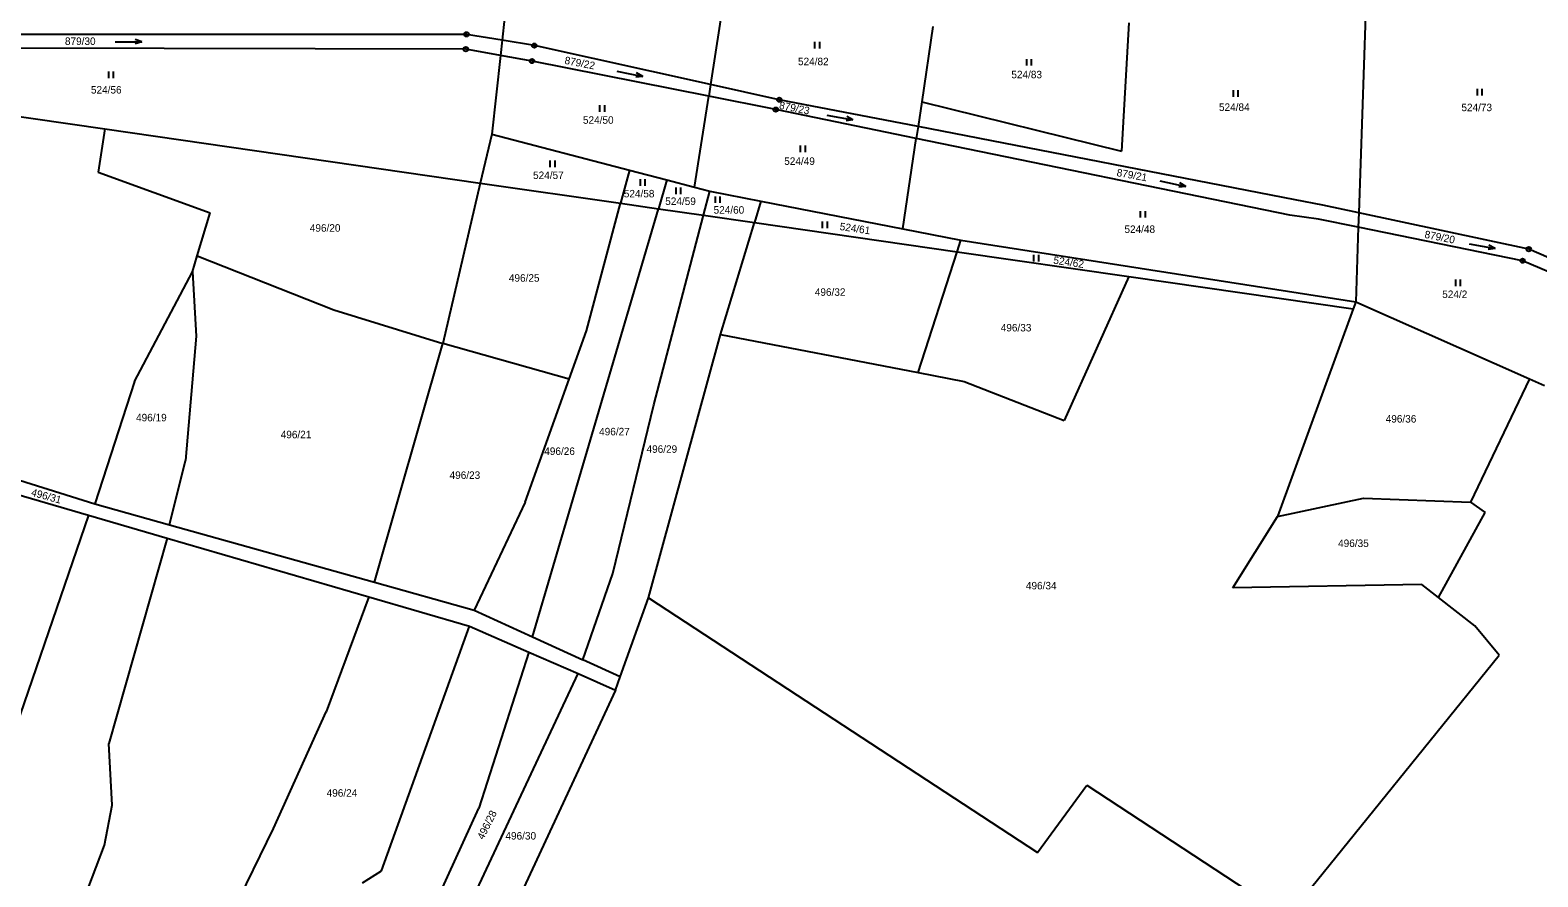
# Model space of a CAD drawing. Extents: x -791032 to -787751, y -1106872 to -1104403.
# Drawn here: x -788433.5 to -788091.4, y -1105584.4 to -1105392.2 of the extents above; entities that cross this region are included whole.
import ezdxf

# ---------------------------------------------------------------- set-up
doc = ezdxf.new("R2010")
doc.units = 0
for name, color, linetype in [('Vrstva 1', 7, 'Continuous'), ('Vrstva 14', 7, 'Continuous'), ('Vrstva 23', 7, 'Continuous'), ('Vrstva 28', 7, 'Continuous')]:
    doc.layers.add(name, color=color, linetype=linetype)

msp = doc.modelspace()

# ---------------------------------------------------------------- linework, layer by layer
at = {"layer": 'Vrstva 1'}
for p, q in [((-788273.84, -1105370.61), (-788279.1, -1105404.59)), ((-788325.25, -1105384.05), (-788326.4, -1105394.54)), ((-788184.19, -1105390.62), (-788185.84, -1105419.71)), ((-788130.47, -1105388.92), (-788132.01, -1105433.71)), ((-788334.47, -1105393.2), (-788437.4, -1105393.2)), ((-788326.4, -1105394.54), (-788334.47, -1105393.2)), ((-788326.4, -1105394.54), (-788326.78, -1105397.98)), ((-788319.07, -1105395.76), (-788326.4, -1105394.54)), ((-788228.63, -1105391.41), (-788231.17, -1105408.51)), ((-788334.62, -1105396.57), (-788437.22, -1105396.3)), ((-788326.78, -1105397.98), (-788334.62, -1105396.57)), ((-788326.78, -1105397.98), (-788328.74, -1105415.89)), ((-788319.59, -1105399.27), (-788326.78, -1105397.98)), ((-788279.1, -1105404.59), (-788319.07, -1105395.76)), ((-788279.51, -1105407.26), (-788319.59, -1105399.27)), ((-788279.1, -1105404.59), (-788279.51, -1105407.26)), ((-788263.5, -1105408.04), (-788279.1, -1105404.59)), ((-788282.7, -1105427.88), (-788279.51, -1105407.26)), ((-788264.29, -1105410.29), (-788279.51, -1105407.26)), ((-788232.01, -1105414.15), (-788263.5, -1105408.04)), ((-788456.18, -1105408.95), (-788416.55, -1105414.66)), ((-788232.41, -1105416.85), (-788264.29, -1105410.29)), ((-788231.17, -1105408.51), (-788232.01, -1105414.15)), ((-788231.17, -1105408.51), (-788185.84, -1105419.71)), ((-788416.55, -1105414.66), (-788418.05, -1105424.46)), ((-788416.55, -1105414.66), (-788331.33, -1105426.95)), ((-788232.01, -1105414.15), (-788232.41, -1105416.85)), ((-788146.48, -1105430.75), (-788232.01, -1105414.15)), ((-788328.74, -1105415.89), (-788331.33, -1105426.95)), ((-788328.74, -1105415.89), (-788297.51, -1105424.02)), ((-788235.44, -1105437.34), (-788232.41, -1105416.85)), ((-788147.63, -1105434.28), (-788232.41, -1105416.85)), ((-788418.05, -1105424.46), (-788392.61, -1105433.72)), ((-788297.51, -1105424.02), (-788299.51, -1105431.54)), ((-788297.51, -1105424.02), (-788289.01, -1105426.24)), ((-788331.33, -1105426.95), (-788339.85, -1105463.39)), ((-788331.33, -1105426.95), (-788299.51, -1105431.54)), ((-788289.01, -1105426.24), (-788290.93, -1105432.78)), ((-788289.01, -1105426.24), (-788282.7, -1105427.88)), ((-788282.7, -1105427.88), (-788279.25, -1105428.78)), ((-788280.68, -1105434.26), (-788279.25, -1105428.78)), ((-788279.25, -1105428.78), (-788267.67, -1105431.04)), ((-788307.25, -1105460.53), (-788299.51, -1105431.54)), ((-788299.51, -1105431.54), (-788290.93, -1105432.78)), ((-788267.67, -1105431.04), (-788269.14, -1105435.92)), ((-788267.67, -1105431.04), (-788235.44, -1105437.34)), ((-788140.18, -1105431.96), (-788146.48, -1105430.75)), ((-788132.01, -1105433.71), (-788140.18, -1105431.96)), ((-788395.55, -1105443.45), (-788392.61, -1105433.72)), ((-788319.47, -1105529.98), (-788290.93, -1105432.78)), ((-788291.96, -1105477.3), (-788280.68, -1105434.26)), ((-788290.93, -1105432.78), (-788280.68, -1105434.26)), ((-788280.68, -1105434.26), (-788269.14, -1105435.92)), ((-788141.19, -1105435.16), (-788147.63, -1105434.28)), ((-788132.12, -1105437), (-788141.19, -1105435.16)), ((-788132.01, -1105433.71), (-788132.12, -1105437)), ((-788093.43, -1105441.97), (-788132.01, -1105433.71)), ((-788276.81, -1105461.37), (-788269.14, -1105435.92)), ((-788269.14, -1105435.92), (-788223.17, -1105442.55)), ((-788235.44, -1105437.34), (-788222.32, -1105439.9)), ((-788132.12, -1105437), (-788132.7, -1105453.89)), ((-788094.84, -1105444.58), (-788132.12, -1105437)), ((-788223.17, -1105442.55), (-788222.32, -1105439.9)), ((-788222.32, -1105439.9), (-788132.7, -1105453.89)), ((-788083.85, -1105446.11), (-788093.43, -1105441.97)), ((-788396.65, -1105447.08), (-788395.55, -1105443.45)), ((-788395.55, -1105443.45), (-788364.54, -1105455.77)), ((-788231.99, -1105469.99), (-788223.17, -1105442.55)), ((-788223.17, -1105442.55), (-788184.2, -1105448.17)), ((-788084.51, -1105449.03), (-788094.84, -1105444.58)), ((-788409.78, -1105472.02), (-788396.65, -1105447.08)), ((-788396.65, -1105447.08), (-788395.83, -1105461.68)), ((-788184.2, -1105448.17), (-788198.85, -1105480.86)), ((-788184.2, -1105448.17), (-788133.29, -1105455.51)), ((-788364.54, -1105455.77), (-788339.85, -1105463.39)), ((-788133.29, -1105455.51), (-788150.45, -1105502.63)), ((-788132.7, -1105453.89), (-788133.29, -1105455.51)), ((-788132.7, -1105453.89), (-788093.3, -1105471.36)), ((-788395.83, -1105461.68), (-788398.24, -1105489.91)), ((-788311.15, -1105471.44), (-788307.25, -1105460.53)), ((-788293.15, -1105521.14), (-788276.81, -1105461.37)), ((-788276.81, -1105461.37), (-788231.99, -1105469.99)), ((-788355.35, -1105517.58), (-788339.85, -1105463.39)), ((-788311.15, -1105471.44), (-788339.85, -1105463.39)), ((-788409.78, -1105472.02), (-788418.82, -1105499.75)), ((-788321.16, -1105499.42), (-788311.15, -1105471.44)), ((-788231.99, -1105469.99), (-788221.58, -1105471.99)), ((-788221.58, -1105471.99), (-788198.85, -1105480.86)), ((-788093.3, -1105471.36), (-788106.66, -1105499.41)), ((-788093.3, -1105471.36), (-788089.84, -1105472.9)), ((-788497.15, -1105475.19), (-788418.82, -1105499.75)), ((-788301.27, -1105515.57), (-788291.96, -1105477.3)), ((-788401.83, -1105504.52), (-788398.24, -1105489.91)), ((-788448.12, -1105494.23), (-788420.23, -1105502.35)), ((-788418.82, -1105499.75), (-788401.83, -1105504.52)), ((-788321.16, -1105499.42), (-788332.7, -1105523.94)), ((-788150.45, -1105502.63), (-788130.98, -1105498.47)), ((-788130.98, -1105498.47), (-788106.66, -1105499.41)), ((-788106.66, -1105499.41), (-788103.33, -1105501.74)), ((-788420.23, -1105502.35), (-788444.81, -1105573.91)), ((-788420.23, -1105502.35), (-788402.42, -1105507.54)), ((-788160.56, -1105518.82), (-788150.45, -1105502.63)), ((-788113.89, -1105521.05), (-788103.33, -1105501.74)), ((-788401.83, -1105504.52), (-788355.35, -1105517.58)), ((-788402.42, -1105507.54), (-788415.59, -1105554.2)), ((-788402.42, -1105507.54), (-788356.66, -1105520.87)), ((-788355.35, -1105517.58), (-788332.7, -1105523.94)), ((-788308.06, -1105535.18), (-788301.27, -1105515.57)), ((-788356.66, -1105520.87), (-788366.34, -1105547.02)), ((-788356.66, -1105520.87), (-788333.78, -1105527.53)), ((-788299.59, -1105539.05), (-788293.15, -1105521.14)), ((-788293.15, -1105521.14), (-788204.92, -1105578.95)), ((-788117.68, -1105518.1), (-788160.56, -1105518.82)), ((-788113.89, -1105521.05), (-788117.68, -1105518.1)), ((-788105.68, -1105527.44), (-788113.89, -1105521.05)), ((-788332.7, -1105523.94), (-788319.47, -1105529.98)), ((-788353.78, -1105583.11), (-788333.78, -1105527.53)), ((-788333.78, -1105527.53), (-788320.32, -1105533.42)), ((-788100.16, -1105534.15), (-788105.68, -1105527.44)), ((-788319.47, -1105529.98), (-788308.06, -1105535.18)), ((-788320.32, -1105533.42), (-788331.7, -1105568.85)), ((-788320.32, -1105533.42), (-788309.15, -1105538.31)), ((-788148.21, -1105593.49), (-788100.16, -1105534.15)), ((-788299.59, -1105539.05), (-788308.06, -1105535.18)), ((-788343.45, -1105611.49), (-788309.15, -1105538.31)), ((-788309.15, -1105538.31), (-788300.66, -1105542.03)), ((-788300.66, -1105542.03), (-788299.59, -1105539.05)), ((-788300.66, -1105542.03), (-788334.81, -1105615.58)), ((-788378.27, -1105573.45), (-788366.34, -1105547.02)), ((-788414.84, -1105568.18), (-788415.59, -1105554.2)), ((-788204.92, -1105578.95), (-788193.74, -1105563.62)), ((-788193.74, -1105563.62), (-788148.21, -1105593.49)), ((-788416.6, -1105577.22), (-788414.84, -1105568.18)), ((-788349.8, -1105608.48), (-788331.7, -1105568.85)), ((-788396.46, -1105610.62), (-788378.27, -1105573.45)), ((-788425.57, -1105600.88), (-788416.6, -1105577.22)), ((-788358.03, -1105585.78), (-788353.78, -1105583.11))]:
    msp.add_line(p, q, dxfattribs=at)
at = {"layer": 'Vrstva 23'}
for p, q in [((-788408.16, -1105394.87), (-788409.66, -1105394.37)), ((-788414.16, -1105394.87), (-788408.16, -1105394.87)), ((-788408.16, -1105394.87), (-788409.66, -1105395.37)), ((-788255.41, -1105396.43), (-788255.41, -1105394.93)), ((-788254.41, -1105394.93), (-788254.41, -1105396.43)), ((-788207.34, -1105400.3), (-788207.34, -1105398.8)), ((-788206.34, -1105398.8), (-788206.34, -1105400.3)), ((-788415.61, -1105403.15), (-788415.61, -1105401.65)), ((-788414.61, -1105401.65), (-788414.61, -1105403.15)), ((-788300.371, -1105401.582), (-788294.488, -1105402.757)), ((-788294.488, -1105402.757), (-788296.056, -1105402.953)), ((-788294.488, -1105402.757), (-788295.861, -1105401.973)), ((-788160.42, -1105407.38), (-788160.42, -1105405.88)), ((-788159.42, -1105405.88), (-788159.42, -1105407.38)), ((-788105.09, -1105407.05), (-788105.09, -1105405.55)), ((-788104.09, -1105405.55), (-788104.09, -1105407.05)), ((-788304.18, -1105410.8), (-788304.18, -1105409.3)), ((-788303.18, -1105409.3), (-788303.18, -1105410.8)), ((-788252.695, -1105411.544), (-788246.784, -1105412.575)), ((-788246.784, -1105412.575), (-788248.348, -1105412.81)), ((-788246.784, -1105412.575), (-788248.176, -1105411.825)), ((-788258.65, -1105419.96), (-788258.65, -1105418.46)), ((-788257.65, -1105418.46), (-788257.65, -1105419.96)), ((-788315.45, -1105423.34), (-788315.45, -1105421.84)), ((-788314.45, -1105421.84), (-788314.45, -1105423.34)), ((-788295.02, -1105427.56), (-788295.02, -1105426.06)), ((-788294.02, -1105426.06), (-788294.02, -1105427.56)), ((-788286.89, -1105429.49), (-788286.89, -1105427.99)), ((-788285.89, -1105427.99), (-788285.89, -1105429.49)), ((-788177.143, -1105426.48), (-788171.276, -1105427.739)), ((-788171.276, -1105427.739), (-788172.848, -1105427.913)), ((-788171.276, -1105427.739), (-788172.638, -1105426.935)), ((-788277.97, -1105431.47), (-788277.97, -1105429.97)), ((-788276.97, -1105429.97), (-788276.97, -1105431.47)), ((-788181.51, -1105434.81), (-788181.51, -1105433.31)), ((-788180.51, -1105433.31), (-788180.51, -1105434.81)), ((-788253.67, -1105437.18), (-788253.67, -1105435.68)), ((-788252.67, -1105435.68), (-788252.67, -1105437.18)), ((-788106.993, -1105440.751), (-788101.086, -1105441.808)), ((-788101.086, -1105441.808), (-788102.651, -1105442.036)), ((-788101.086, -1105441.808), (-788102.475, -1105441.051)), ((-788205.71, -1105444.78), (-788205.71, -1105443.28)), ((-788204.71, -1105443.28), (-788204.71, -1105444.78)), ((-788110, -1105450.35), (-788110, -1105448.85)), ((-788109, -1105448.85), (-788109, -1105450.35))]:
    msp.add_line(p, q, dxfattribs=at)
at = {"layer": 'Vrstva 28'}
for centre, radius in [((-788334.47, -1105393.2), 0.5), ((-788334.47, -1105393.2), 0.01), ((-788334.62, -1105396.57), 0.5), ((-788334.62, -1105396.57), 0.01), ((-788319.07, -1105395.76), 0.5), ((-788319.07, -1105395.76), 0.01), ((-788319.59, -1105399.27), 0.5), ((-788319.59, -1105399.27), 0.01), ((-788263.5, -1105408.04), 0.5), ((-788263.5, -1105408.04), 0.01), ((-788264.29, -1105410.29), 0.5), ((-788264.29, -1105410.29), 0.01), ((-788093.43, -1105441.97), 0.5), ((-788093.43, -1105441.97), 0.01), ((-788094.84, -1105444.58), 0.5), ((-788094.84, -1105444.58), 0.01)]:
    msp.add_circle(centre, radius, dxfattribs=at)

# ---------------------------------------------------------------- texts
at = {"layer": 'Vrstva 14'}
for s, p in [('879/30', (-788425.575, -1105395.6)), ('524/82', (-788259.251, -1105400.21)), ('524/83', (-788210.842, -1105403.17)), ('524/56', (-788419.678, -1105406.64)), ('524/50', (-788308.047, -1105413.5)), ('524/84', (-788163.737, -1105410.58)), ('524/73', (-788108.728, -1105410.64)), ('524/49', (-788262.378, -1105422.83)), ('524/57', (-788319.365, -1105426.04)), ('524/58', (-788298.778, -1105430.21)), ('524/59', (-788289.378, -1105431.93)), ('524/60', (-788278.401, -1105433.9)), ('496/20', (-788370.015, -1105438)), ('524/48', (-788185.187, -1105438.28)), ('496/25', (-788324.852, -1105449.35)), ('496/32', (-788255.436, -1105452.55)), ('524/2', (-788113.082, -1105453.05)), ('496/33', (-788213.246, -1105460.64)), ('496/19', (-788409.439, -1105481.04)), ('496/36', (-788125.906, -1105481.32)), ('496/21', (-788376.619, -1105484.89)), ('496/27', (-788304.372, -1105484.22)), ('496/26', (-788316.826, -1105488.67)), ('496/29', (-788293.616, -1105488.19)), ('496/23', (-788338.306, -1105494.11)), ('496/35', (-788136.702, -1105509.57)), ('496/34', (-788207.542, -1105519.19)), ('496/24', (-788366.201, -1105566.25)), ('496/30', (-788325.635, -1105575.98))]:
    msp.add_text(s, height=1.7, dxfattribs=at).set_placement(p)
for s, rotation, p in [('879/22', 349.08462, (-788312.329, -1105399.872)), ('879/23', 348.70752, (-788263.633, -1105410.07)), ('879/21', 349.96644, (-788187.047, -1105425.356)), ('524/61', 351.78075, (-788249.874, -1105437.605)), ('879/20', 348.79653, (-788117.204, -1105439.369)), ('524/62', 351.78075, (-788201.388, -1105445.253)), ('496/31', 344.46645, (-788433.362, -1105497.893)), ('496/28', 63.43497, (-788330.629, -1105576.119))]:
    msp.add_text(s, height=1.7, rotation=rotation, dxfattribs=at).set_placement(p)

doc.saveas('drawing.dxf')
